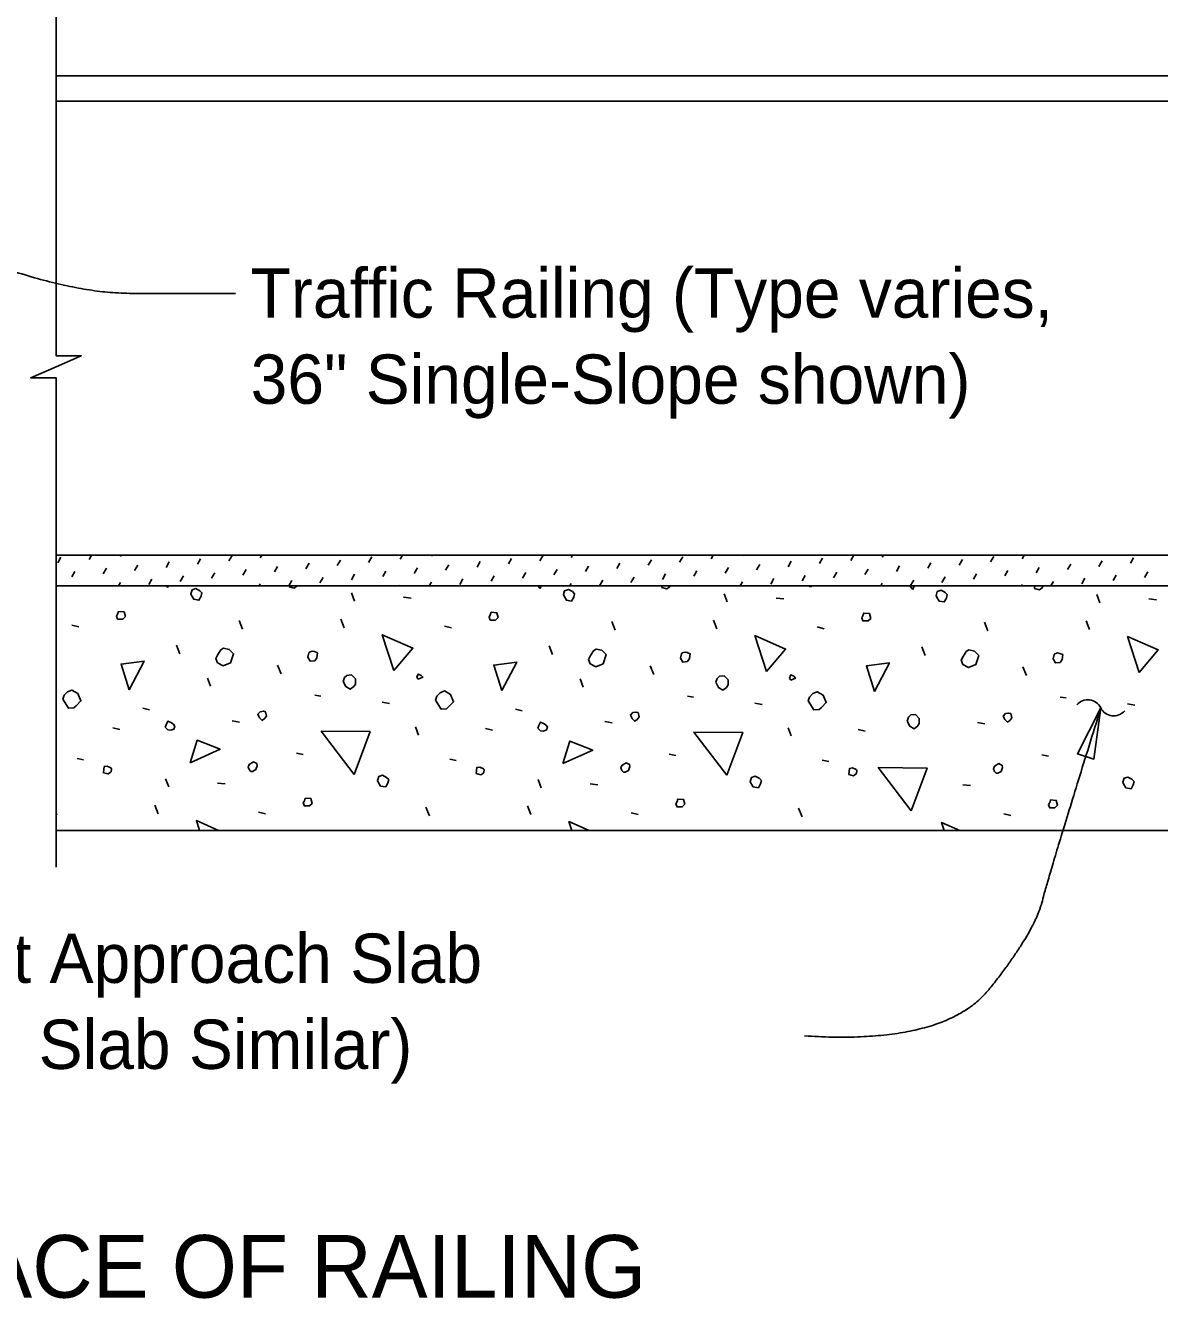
# Model space of a CAD drawing. Extents: x 0 to 41, y -96 to 25.
# Drawn here: x 16.84 to 21.47, y 9.6 to 14.8 of the extents above; entities that cross this region are included whole.
import ezdxf

# ---------------------------------------------------------------- set-up
doc = ezdxf.new("R2010")
doc.units = 0
for name, color, linetype in [('Dimension', 7, 'Continuous'), ('Miscellaneous', 7, 'Continuous'), ('SupstrConc', 7, 'Continuous')]:
    doc.layers.add(name, color=color, linetype=linetype)

msp = doc.modelspace()

# ---------------------------------------------------------------- linework, layer by layer
at = {"layer": 'Dimension'}
msp.add_lwpolyline([(16.9607, 15.3052), (16.9607, 13.4544), (17.064, 13.4544), (16.9607, 13.4094), (16.8574, 13.3644), (16.9607, 13.3644), (16.9607, 11.3636)], dxfattribs=at)
msp.add_lwpolyline([(21.2333, 12.0144), (21.1375, 11.8262), (21.2049, 11.8051)], close=True, dxfattribs=at)
for centre, start, end in [((21.1793, 11.9876), 26.8413, 138.5686), ((21.2857, 12.0415), 206.8413, 318.5686)]:
    msp.add_arc(centre, 0.0596, start, end, dxfattribs=at)
for points in [[(17.694, 13.7089), (17.6241, 13.7089), (16.9246, 13.7089), (16.367, 13.9658)], [(20.0218, 10.6728), (20.5947, 10.6363), (20.9596, 11.093), (21.0259, 11.3503), (21.2332, 12.0144)]]:
    msp.add_open_spline(points, degree=2, dxfattribs=at)
at = {"layer": 'Miscellaneous'}
for p, q in [((16.9674, 12.6078), (16.9804, 12.6302)), ((17.0959, 12.6208), (17.1062, 12.6385)), ((17.2243, 12.6337), (17.2271, 12.6385)), ((17.2821, 12.576), (17.2951, 12.5984)), ((17.4105, 12.5889), (17.4235, 12.6113)), ((17.539, 12.6019), (17.552, 12.6243)), ((17.6675, 12.6149), (17.6804, 12.6373)), ((17.7959, 12.6278), (17.8021, 12.6385)), ((17.9821, 12.583), (17.9951, 12.6054)), ((18.1106, 12.596), (18.1235, 12.6184)), ((18.239, 12.609), (18.252, 12.6314)), ((18.3675, 12.6219), (18.3771, 12.6385)), ((18.496, 12.6349), (18.498, 12.6385)), ((18.5537, 12.5771), (18.5667, 12.5995)), ((18.6822, 12.5901), (18.6951, 12.6125)), ((18.8106, 12.6031), (18.8236, 12.6255)), ((18.9391, 12.616), (18.952, 12.6384)), ((19.0675, 12.629), (19.073, 12.6385)), ((19.2537, 12.5842), (19.2667, 12.6066)), ((19.3822, 12.5972), (19.3952, 12.6196)), ((19.5107, 12.6101), (19.5236, 12.6325)), ((19.6391, 12.6231), (19.648, 12.6385)), ((19.7676, 12.6361), (19.769, 12.6385)), ((19.8253, 12.5783), (19.8383, 12.6007)), ((19.9538, 12.5913), (19.9667, 12.6137)), ((20.0822, 12.6043), (20.0952, 12.6266)), ((20.2107, 12.6172), (20.223, 12.6385)), ((20.3391, 12.6302), (20.344, 12.6385)), ((20.5254, 12.5854), (20.5383, 12.6078)), ((20.6538, 12.5984), (20.6668, 12.6208)), ((20.7823, 12.6113), (20.7952, 12.6337)), ((20.9107, 12.6243), (20.9189, 12.6385)), ((21.0392, 12.6373), (21.0399, 12.6385)), ((21.0969, 12.5795), (21.1099, 12.6019)), ((21.2254, 12.5925), (21.2384, 12.6149)), ((21.3538, 12.6054), (21.3668, 12.6278)), ((17.0252, 12.55), (17.0381, 12.5724)), ((17.1536, 12.563), (17.1666, 12.5854)), ((17.4683, 12.5312), (17.4813, 12.5536)), ((17.5968, 12.5441), (17.6097, 12.5665)), ((17.7252, 12.5571), (17.7382, 12.5795)), ((17.8537, 12.5701), (17.8666, 12.5925)), ((18.0399, 12.5253), (18.0528, 12.5477)), ((18.1683, 12.5383), (18.1813, 12.5606)), ((18.2968, 12.5512), (18.3098, 12.5736)), ((18.4252, 12.5642), (18.4382, 12.5866)), ((18.7399, 12.5324), (18.7529, 12.5548)), ((18.8684, 12.5453), (18.8813, 12.5677)), ((18.9968, 12.5583), (19.0098, 12.5807)), ((19.1253, 12.5713), (19.1382, 12.5936)), ((19.3115, 12.5265), (19.3245, 12.5489)), ((19.4399, 12.5394), (19.4529, 12.5618)), ((19.5684, 12.5524), (19.5814, 12.5748)), ((19.6969, 12.5654), (19.7098, 12.5878)), ((20.0115, 12.5335), (20.0245, 12.5559)), ((20.14, 12.5465), (20.1529, 12.5689)), ((20.2684, 12.5595), (20.2814, 12.5819)), ((20.3969, 12.5724), (20.4099, 12.5948)), ((20.5831, 12.5276), (20.5961, 12.55)), ((20.7116, 12.5406), (20.7245, 12.563)), ((20.84, 12.5536), (20.853, 12.576)), ((20.9685, 12.5665), (20.9814, 12.5889)), ((21.2831, 12.5347), (21.2961, 12.5571)), ((21.4116, 12.5477), (21.4246, 12.5701)), ((17.2162, 12.5135), (17.2243, 12.5276)), ((17.3398, 12.5182), (17.3528, 12.5406)), ((17.7911, 12.5135), (17.7959, 12.5218)), ((17.9121, 12.5135), (17.9244, 12.5347)), ((18.3661, 12.5135), (18.3675, 12.5159)), ((18.4871, 12.5135), (18.496, 12.5288)), ((18.6115, 12.5194), (18.6244, 12.5418)), ((19.0621, 12.5135), (19.0675, 12.5229)), ((19.183, 12.5135), (19.196, 12.5359)), ((19.758, 12.5135), (19.7676, 12.53)), ((19.8831, 12.5206), (19.896, 12.543)), ((20.333, 12.5135), (20.3391, 12.5241)), ((20.4546, 12.5147), (20.4676, 12.5371)), ((20.908, 12.5135), (20.9107, 12.5182)), ((21.029, 12.5135), (21.0392, 12.5312)), ((21.1547, 12.5218), (21.1676, 12.5441)), ((18.1814, 12.4511), (18.169, 12.4847)), ((18.3811, 12.467), (18.413, 12.4635)), ((19.7052, 12.4476), (19.6928, 12.4812)), ((19.905, 12.4635), (19.9368, 12.4599)), ((21.229, 12.444), (21.2166, 12.4776)), ((21.4288, 12.4599), (21.4606, 12.4564)), ((17.0253, 12.3521), (17.0536, 12.345)), ((17.7235, 12.3362), (17.7094, 12.3715)), ((18.139, 12.3415), (18.1248, 12.3769)), ((18.5491, 12.3486), (18.5774, 12.3415)), ((19.2474, 12.3327), (19.2332, 12.368)), ((19.6628, 12.338), (19.6486, 12.3733)), ((20.0729, 12.345), (20.1012, 12.338)), ((20.7712, 12.3291), (20.757, 12.3645)), ((21.1866, 12.3344), (21.1725, 12.3698)), ((17.4672, 12.2354), (17.4531, 12.2708)), ((18.991, 12.2319), (18.9769, 12.2673)), ((20.5148, 12.2284), (20.5007, 12.2637)), ((17.8809, 12.1541), (17.8667, 12.1895)), ((19.4047, 12.1506), (19.3905, 12.1859)), ((20.9285, 12.147), (20.9144, 12.1824)), ((17.5927, 12.1028), (17.5804, 12.1364)), ((19.1165, 12.0993), (19.1042, 12.1329)), ((18.0188, 12.0657), (18.0435, 12.0622)), ((18.2945, 12.0374), (18.3246, 12.0321)), ((19.5426, 12.0622), (19.5673, 12.0587)), ((19.8183, 12.0339), (19.8484, 12.0286)), ((21.0664, 12.0587), (21.0911, 12.0551)), ((21.3422, 12.0304), (21.3722, 12.0251)), ((17.3152, 12.0127), (17.3435, 12.0056)), ((18.839, 12.0092), (18.8673, 12.0021)), ((17.1932, 11.9331), (17.2215, 11.9261)), ((17.6811, 11.9614), (17.7112, 11.9561)), ((18.443, 11.9031), (18.4306, 11.9367)), ((18.717, 11.9296), (18.7453, 11.9225)), ((19.2049, 11.9579), (19.235, 11.9526)), ((19.9668, 11.8996), (19.9545, 11.9331)), ((20.2408, 11.9261), (20.2691, 11.919)), ((20.7287, 11.9544), (20.7588, 11.9491)), ((17.9445, 11.8288), (17.971, 11.8235)), ((19.4683, 11.8253), (19.4948, 11.82)), ((20.9921, 11.8218), (21.0187, 11.8165)), ((17.0465, 11.8076), (17.073, 11.8023)), ((18.5703, 11.8041), (18.5968, 11.7988)), ((20.0941, 11.8006), (20.1206, 11.7953)), ((17.4213, 11.691), (17.4089, 11.7245)), ((18.9451, 11.6874), (18.9327, 11.721)), ((17.621, 11.7069), (17.6528, 11.7033)), ((19.1448, 11.7033), (19.1766, 11.6998)), ((20.6686, 11.6998), (20.7005, 11.6963)), ((17.3788, 11.5814), (17.3647, 11.6167)), ((18.9026, 11.5778), (18.8885, 11.6132)), ((16.9634, 11.5761), (16.9607, 11.5829)), ((17.7889, 11.5884), (17.8172, 11.5814)), ((18.4872, 11.5725), (18.4731, 11.6079)), ((19.3128, 11.5849), (19.341, 11.5778)), ((20.011, 11.569), (19.9969, 11.6043)), ((20.8366, 11.5814), (20.8649, 11.5743))]:
    msp.add_line(p, q, dxfattribs=at)
for points in [[(17.4159, 12.5059), (17.4102, 12.5135)], [(17.4188, 12.5135), (17.4159, 12.5059)], [(17.5149, 12.4741), (17.5238, 12.4582), (17.545, 12.4546), (17.5538, 12.4705), (17.5574, 12.4847), (17.5485, 12.4935), (17.5326, 12.5024), (17.5167, 12.4971), (17.5114, 12.4812), (17.5149, 12.4741)], [(17.9145, 12.5094), (17.9339, 12.5041), (17.9463, 12.513), (17.9464, 12.5135)], [(17.915, 12.5135), (17.9145, 12.5094)], [(18.9398, 12.5024), (18.9313, 12.5135)], [(18.9439, 12.5135), (18.9398, 12.5024)], [(19.0388, 12.4705), (19.0476, 12.4546), (19.0688, 12.4511), (19.0776, 12.467), (19.0812, 12.4812), (19.0723, 12.49), (19.0564, 12.4988), (19.0405, 12.4935), (19.0352, 12.4776), (19.0388, 12.4705)], [(19.4383, 12.5059), (19.4577, 12.5006), (19.4701, 12.5094), (19.4707, 12.5135)], [(19.4394, 12.5135), (19.4383, 12.5059)], [(20.0388, 12.5135), (20.0411, 12.5112)], [(20.0411, 12.5112), (20.0482, 12.5112), (20.0528, 12.5135)], [(20.4636, 12.4988), (20.4524, 12.5135)], [(20.4691, 12.5135), (20.4636, 12.4988)], [(20.5626, 12.467), (20.5714, 12.4511), (20.5926, 12.4476), (20.6015, 12.4635), (20.605, 12.4776), (20.5962, 12.4865), (20.5803, 12.4953), (20.5643, 12.49), (20.559, 12.4741), (20.5626, 12.467)], [(20.9621, 12.5024), (20.9815, 12.4971), (20.9939, 12.5059), (20.995, 12.5135)], [(20.9637, 12.5135), (20.9621, 12.5024)], [(17.2127, 12.3769), (17.2339, 12.3769), (17.2445, 12.3875), (17.2392, 12.4069), (17.2162, 12.4087), (17.2127, 12.3981), (17.2074, 12.3892), (17.2127, 12.3769), (17.2091, 12.3804)], [(18.7365, 12.3733), (18.7577, 12.3733), (18.7683, 12.3839), (18.763, 12.4034), (18.74, 12.4051), (18.7365, 12.3945), (18.7312, 12.3857), (18.7365, 12.3733), (18.7329, 12.3769)], [(20.2603, 12.3698), (20.2815, 12.3698), (20.2921, 12.3804), (20.2868, 12.3998), (20.2638, 12.4016), (20.2603, 12.391), (20.255, 12.3822), (20.2603, 12.3698), (20.2568, 12.3733)], [(18.3423, 12.1665), (18.2945, 12.3132), (18.42, 12.2584), (18.3423, 12.1665)], [(19.8661, 12.163), (19.8183, 12.3097), (19.9439, 12.2549), (19.8661, 12.163)], [(21.3899, 12.1594), (21.3422, 12.3061), (21.4677, 12.2513), (21.3899, 12.1594)], [(17.621, 12.1983), (17.644, 12.1859), (17.674, 12.1983), (17.6864, 12.2354), (17.6687, 12.2531), (17.6458, 12.2584), (17.6352, 12.2513), (17.6228, 12.2319), (17.6139, 12.216), (17.621, 12.1983)], [(17.9905, 12.2213), (17.9993, 12.2054), (18.0188, 12.2071), (18.0276, 12.2195), (18.0294, 12.239), (18.017, 12.2443), (18.0082, 12.246), (17.9975, 12.2425), (17.994, 12.239), (17.9905, 12.2213)], [(19.1448, 12.1948), (19.1678, 12.1824), (19.1979, 12.1948), (19.2102, 12.2319), (19.1926, 12.2496), (19.1696, 12.2549), (19.159, 12.2478), (19.1466, 12.2284), (19.1378, 12.2125), (19.1448, 12.1948)], [(19.5143, 12.2178), (19.5231, 12.2018), (19.5426, 12.2036), (19.5514, 12.216), (19.5532, 12.2354), (19.5408, 12.2407), (19.532, 12.2425), (19.5214, 12.239), (19.5178, 12.2354), (19.5143, 12.2178)], [(20.6686, 12.1912), (20.6916, 12.1789), (20.7217, 12.1912), (20.734, 12.2284), (20.7164, 12.246), (20.6934, 12.2513), (20.6828, 12.2443), (20.6704, 12.2248), (20.6616, 12.2089), (20.6686, 12.1912)], [(21.0381, 12.2142), (21.0469, 12.1983), (21.0664, 12.2001), (21.0752, 12.2125), (21.077, 12.2319), (21.0646, 12.2372), (21.0558, 12.239), (21.0452, 12.2354), (21.0416, 12.2319), (21.0381, 12.2142)], [(17.2604, 12.0887), (17.2268, 12.193), (17.3205, 12.2054), (17.2604, 12.0887)], [(18.7842, 12.0852), (18.7506, 12.1895), (18.8443, 12.2018), (18.7842, 12.0852)], [(20.308, 12.0816), (20.2744, 12.1859), (20.3681, 12.1983), (20.308, 12.0816)], [(18.1354, 12.1223), (18.146, 12.1011), (18.1637, 12.0905), (18.1779, 12.1011), (18.1849, 12.1117), (18.1849, 12.1329), (18.169, 12.1488), (18.1496, 12.147), (18.1407, 12.1382), (18.1354, 12.1223)], [(18.4413, 12.1311), (18.4607, 12.14), (18.4536, 12.147), (18.4413, 12.1523), (18.436, 12.14), (18.4413, 12.1311)], [(19.6592, 12.1188), (19.6699, 12.0975), (19.6875, 12.0869), (19.7017, 12.0975), (19.7087, 12.1082), (19.7087, 12.1294), (19.6928, 12.1453), (19.6734, 12.1435), (19.6645, 12.1347), (19.6592, 12.1188)], [(19.9651, 12.1276), (19.9845, 12.1364), (19.9774, 12.1435), (19.9651, 12.1488), (19.9598, 12.1364), (19.9651, 12.1276)], [(16.9881, 12.0498), (17.0111, 12.0127), (17.0341, 12.0145), (17.043, 12.0233), (17.0624, 12.0427), (17.05, 12.0728), (17.0253, 12.0869), (17.0076, 12.0799), (16.9935, 12.0657), (16.9881, 12.0498)], [(18.512, 12.0463), (18.5349, 12.0092), (18.5579, 12.0109), (18.5668, 12.0198), (18.5862, 12.0392), (18.5738, 12.0693), (18.5491, 12.0834), (18.5314, 12.0763), (18.5173, 12.0622), (18.512, 12.0463)], [(20.0358, 12.0427), (20.0588, 12.0056), (20.0817, 12.0074), (20.0906, 12.0162), (20.11, 12.0357), (20.0977, 12.0657), (20.0729, 12.0799), (20.0552, 12.0728), (20.0411, 12.0587), (20.0358, 12.0427)], [(17.7925, 11.9738), (17.8031, 11.9632), (17.8137, 11.9703), (17.8208, 11.9809), (17.8172, 11.9986), (17.8084, 12.0003), (17.796, 11.9986), (17.7854, 11.9879), (17.7925, 11.9738)], [(19.3163, 11.9703), (19.3269, 11.9597), (19.3375, 11.9667), (19.3446, 11.9773), (19.341, 11.995), (19.3322, 11.9968), (19.3198, 11.995), (19.3092, 11.9844), (19.3163, 11.9703)], [(20.4412, 11.9606), (20.4518, 11.9394), (20.4695, 11.9288), (20.4836, 11.9394), (20.4907, 11.95), (20.4907, 11.9712), (20.4748, 11.9871), (20.4554, 11.9853), (20.4465, 11.9765), (20.4412, 11.9606)], [(20.8401, 11.9667), (20.8507, 11.9561), (20.8613, 11.9632), (20.8684, 11.9738), (20.8649, 11.9915), (20.856, 11.9932), (20.8436, 11.9915), (20.833, 11.9809), (20.8401, 11.9667)], [(17.4177, 11.9243), (17.4301, 11.9225), (17.4425, 11.9278), (17.446, 11.9384), (17.4407, 11.9473), (17.4301, 11.9544), (17.4177, 11.9597), (17.4106, 11.9455), (17.4071, 11.9349), (17.4177, 11.9243)], [(18.9415, 11.9208), (18.9539, 11.919), (18.9663, 11.9243), (18.9698, 11.9349), (18.9645, 11.9438), (18.9539, 11.9508), (18.9415, 11.9561), (18.9345, 11.942), (18.9309, 11.9314), (18.9415, 11.9208)], [(17.5096, 11.79), (17.5379, 11.8819), (17.6316, 11.8448), (17.5096, 11.79)], [(18.1796, 11.7422), (18.0453, 11.919), (18.245, 11.9172), (18.1796, 11.7422)], [(19.0335, 11.7864), (19.0617, 11.8783), (19.1554, 11.8412), (19.0335, 11.7864)], [(19.7034, 11.7387), (19.5691, 11.9155), (19.7688, 11.9137), (19.7034, 11.7387)], [(17.1543, 11.7493), (17.1738, 11.744), (17.1861, 11.7528), (17.1879, 11.7652), (17.1844, 11.7687), (17.1702, 11.7758), (17.1579, 11.774), (17.1561, 11.7617), (17.1543, 11.7493)], [(17.7571, 11.7546), (17.7642, 11.7546), (17.7783, 11.7617), (17.7836, 11.7776), (17.7819, 11.7864), (17.7677, 11.7935), (17.7501, 11.7829), (17.7465, 11.7723), (17.7501, 11.7617), (17.7571, 11.7546)], [(18.6781, 11.7458), (18.6976, 11.7405), (18.71, 11.7493), (18.7117, 11.7617), (18.7082, 11.7652), (18.694, 11.7723), (18.6817, 11.7705), (18.6799, 11.7581), (18.6781, 11.7458)], [(19.2809, 11.7511), (19.288, 11.7511), (19.3022, 11.7581), (19.3075, 11.774), (19.3057, 11.7829), (19.2915, 11.79), (19.2739, 11.7793), (19.2703, 11.7687), (19.2739, 11.7581), (19.2809, 11.7511)], [(20.2019, 11.7422), (20.2214, 11.7369), (20.2338, 11.7458), (20.2355, 11.7581), (20.232, 11.7617), (20.2179, 11.7687), (20.2055, 11.767), (20.2037, 11.7546), (20.2019, 11.7422)], [(20.4573, 11.5934), (20.323, 11.7702), (20.5227, 11.7684), (20.4573, 11.5934)], [(20.8048, 11.7475), (20.8118, 11.7475), (20.826, 11.7546), (20.8313, 11.7705), (20.8295, 11.7793), (20.8154, 11.7864), (20.7977, 11.7758), (20.7942, 11.7652), (20.7977, 11.7546), (20.8048, 11.7475)], [(18.2786, 11.7104), (18.2875, 11.6945), (18.3087, 11.691), (18.3175, 11.7069), (18.321, 11.721), (18.3122, 11.7299), (18.2963, 11.7387), (18.2804, 11.7334), (18.2751, 11.7175), (18.2786, 11.7104)], [(19.8024, 11.7069), (19.8113, 11.691), (19.8325, 11.6874), (19.8413, 11.7033), (19.8449, 11.7175), (19.836, 11.7263), (19.8201, 11.7352), (19.8042, 11.7299), (19.7989, 11.7139), (19.8024, 11.7069)], [(21.3262, 11.7033), (21.3351, 11.6874), (21.3563, 11.6839), (21.3651, 11.6998), (21.3687, 11.7139), (21.3598, 11.7228), (21.3439, 11.7316), (21.328, 11.7263), (21.3227, 11.7104), (21.3262, 11.7033)], [(17.9763, 11.6132), (17.9975, 11.6132), (18.0082, 11.6238), (18.0028, 11.6432), (17.9799, 11.645), (17.9763, 11.6344), (17.971, 11.6256), (17.9763, 11.6132), (17.9728, 11.6167)], [(19.5001, 11.6096), (19.5214, 11.6096), (19.532, 11.6202), (19.5267, 11.6397), (19.5037, 11.6415), (19.5001, 11.6309), (19.4948, 11.622), (19.5001, 11.6096), (19.4966, 11.6132)], [(21.024, 11.6061), (21.0452, 11.6061), (21.0558, 11.6167), (21.0505, 11.6362), (21.0275, 11.6379), (21.024, 11.6273), (21.0187, 11.6185), (21.024, 11.6061), (21.0204, 11.6096)], [(17.5473, 11.5135), (17.5344, 11.5531), (17.625, 11.5135)], [(19.0699, 11.5135), (19.0582, 11.5495), (19.1407, 11.5135)], [(20.5926, 11.5135), (20.582, 11.546), (20.6564, 11.5135)]]:
    msp.add_lwpolyline(points, dxfattribs=at)
at = {"layer": 'SupstrConc'}
for p, q in [((16.9607, 14.5986), (24.2625, 14.5986)), ((16.9607, 14.4945), (24.2625, 14.4945)), ((16.9607, 12.6385), (24.2625, 12.6385)), ((22.2625, 12.5135), (16.9607, 12.5135)), ((22.6452, 11.5135), (16.9607, 11.5135))]:
    msp.add_line(p, q, dxfattribs=at)

# ---------------------------------------------------------------- texts
at = {"layer": 'Dimension'}
for s, height, p in [('Traffic Railing (Type varies,', 0.2016, (17.7566, 13.6097)), ('36" Single-Slope shown)', 0.2016, (17.7566, 13.2577)), ('Approach Slab (Flexible Pavement Approach Slab ', 0.2016, (12.7086, 10.8899)), ('Shown, Rigid Pavement Approach Slab Similar)', 0.2016, (12.7086, 10.5379)), ('ELEVATION OF OUTSIDE FACE OF RAILING', 0.256001, (12.2221, 9.6027))]:
    msp.add_text(s, height=height, dxfattribs=at).set_placement(p)

doc.saveas('drawing.dxf')
